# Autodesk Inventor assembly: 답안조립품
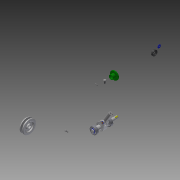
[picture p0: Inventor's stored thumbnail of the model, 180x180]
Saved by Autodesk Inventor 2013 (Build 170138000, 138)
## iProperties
Created: 2016-01
Part Number: 답안조립품
Document SubType Name: Assembly
Designer: Administrator
Author: Administrator
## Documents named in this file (19)
- C:\Users\Administrator\Desktop\460127V1018\답안조립품.iam
- C:\Users\Administrator\Desktop\460127V1018\1본체.ipt
- C:\Users\Administrator\Desktop\460127V1018\V-벨트풀리.ipt
- C:\Users\Administrator\Desktop\460127V1018\고정핀.ipt
- C:\Users\Administrator\Desktop\460127V1018\뒤커버.ipt
- C:\Users\Administrator\Desktop\460127V1018\링크.ipt
- C:\Users\Administrator\Desktop\460127V1018\멈춤링 6 x 5.ipt
- C:\Users\Administrator\Desktop\460127V1018\멈춤링 15 x 1.ipt
- C:\Users\Administrator\Desktop\460127V1018\베어링 15 x 35 x 11.ipt
- C:\Users\Administrator\Desktop\460127V1018\볼트 M3 x 8.ipt
- C:\Users\Administrator\Desktop\460127V1018\볼트 M4 x 10.ipt
- C:\Users\Administrator\Desktop\460127V1018\볼트 M6 x 12.ipt
- C:\Users\Administrator\Desktop\460127V1018\상부부시.ipt
- C:\Users\Administrator\Desktop\460127V1018\슬라이드바.ipt
- C:\Users\Administrator\Desktop\460127V1018\앞커버.ipt
- C:\Users\Administrator\Desktop\460127V1018\오일실 15 25 7.ipt
- C:\Users\Administrator\Desktop\460127V1018\와셔.ipt
- C:\Users\Administrator\Desktop\460127V1018\키 5 x 5 x 14.ipt
- C:\Users\Administrator\Desktop\460127V1018\편심축.ipt
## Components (6 placed, 6 different names)
1. 1본체:1
2. V-벨트풀리:1
3. 고정핀:1
4. ISO 4762 M3 x 8:1
5. ISO 4762 M4 x 10:1
6. ISO 4018 M6 x 12:1
